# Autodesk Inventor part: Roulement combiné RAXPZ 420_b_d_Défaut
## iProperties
Shininess: 64.0
Length Units: 11269
Angle Units: 11279
Time Units: 11290
Mass Units: 11283
Length Display Precision: 3
Angle Display Precision: 2
Compacted: True
Part Number: Roulement combiné RAXPZ 420_b_d_Défaut
Document SubType Name: Modeling
Created: 2006-01
Material: Par défaut
Designer: riri
Density: 0.0
Volumn: 0.0
Area: 0.0
PropertySet Name: Model Information
Control State: 0
Master: False
Checked Out: False
Author: riri
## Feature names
1. Base1
